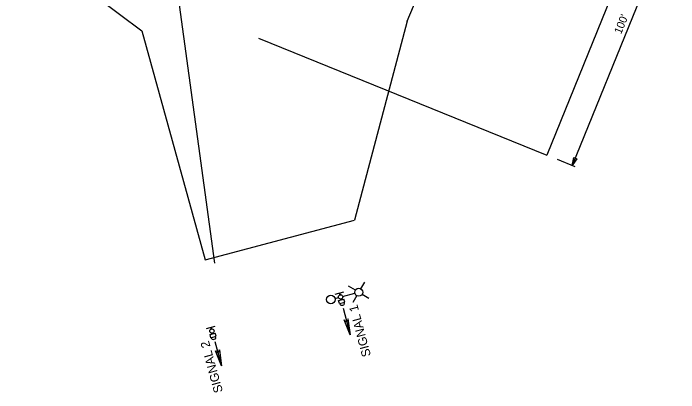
# Model space of a CAD drawing. Extents: x 2047712 to 2051245, y 280285 to 283042.
# Drawn here: x 2047805.4 to 2048040.6, y 281659.1 to 281793.2 of the extents above; entities that cross this region are included whole.
import ezdxf

# ---------------------------------------------------------------- set-up
doc = ezdxf.new("R2010")
doc.units = 0
for name, color, linetype in [('RD_X_GR_Rt', 7, 'Continuous'), ('RW_X_CL_100_Distances', 7, 'Continuous'), ('RW_X_CL_100_Stations', 7, 'Continuous'), ('SV_Control_Point', 7, 'Continuous')]:
    doc.layers.add(name, color=color, linetype=linetype)

msp = doc.modelspace()

# ---------------------------------------------------------------- linework, layer by layer
at = {"layer": 'RD_X_GR_Rt'}
for p, q in [((2048031.58, 281835.68), (2047993.97, 281743.02)), ((2048040.59, 281832.02), (2048002.98, 281739.36)), ((2047892.05, 281784.39), (2047993.97, 281743.02)), ((2047997.58, 281741.56), (2048003.91, 281738.99))]:
    msp.add_line(p, q, dxfattribs=at)
msp.add_lwpolyline([(2048003.51, 281742.17), (2048004.55, 281741.75), (2048002.98, 281739.36)], close=True, dxfattribs=at)
at = {"layer": 'RW_X_CL_100_Distances'}
msp.add_line((2047876.59, 281704.89), (2047860.7, 281821.73), dxfattribs=at)
at = {"layer": 'RW_X_CL_100_Stations'}
for p, q in [((2047928.22, 281695.78), (2047929.65, 281698.19)), ((2047926.31, 281695.28), (2047923.89, 281696.71)), ((2047919.14, 281693.85), (2047922.27, 281694.69)), ((2047920.59, 281694.24), (2047920.76, 281693.6)), ((2047920.82, 281694.3), (2047921, 281693.66)), ((2047921.81, 281693.1), (2047926.16, 281694.22)), ((2047926.8, 281693.37), (2047925.38, 281690.95)), ((2047928.72, 281693.86), (2047931.13, 281692.44)), ((2047919.12, 281692.4), (2047920.34, 281692.71)), ((2047920.4, 281691.68), (2047922.27, 281692.18)), ((2047920.69, 281690.57), (2047920.4, 281691.68)), ((2047920.69, 281690.57), (2047922.57, 281691.07)), ((2047921.15, 281692.16), (2047921.22, 281691.9)), ((2047921.38, 281692.22), (2047921.45, 281691.96)), ((2047922.57, 281691.07), (2047922.27, 281692.18)), ((2047922.45, 281690.54), (2047922.33, 281691)), ((2047921.06, 281690.16), (2047920.94, 281690.63)), ((2047921.99, 281688.91), (2047924.47, 281679.57)), ((2047924.47, 281679.57), (2047922.35, 281684.83)), ((2047923.7, 281685.19), (2047924.47, 281679.57)), ((2047873.66, 281681.76), (2047876.78, 281682.63)), ((2047875.11, 281682.16), (2047875.29, 281681.52)), ((2047875.34, 281682.22), (2047875.52, 281681.59)), ((2047874.94, 281679.6), (2047876.81, 281680.12)), ((2047875.25, 281678.5), (2047874.94, 281679.6)), ((2047875.69, 281680.08), (2047875.76, 281679.83)), ((2047875.92, 281680.15), (2047875.99, 281679.89)), ((2047877.12, 281679.02), (2047876.81, 281680.12)), ((2047875.25, 281678.5), (2047877.12, 281679.02)), ((2047875.62, 281678.09), (2047875.49, 281678.56)), ((2047876.67, 281677.22), (2047879.06, 281668.6)), ((2047877.01, 281678.48), (2047876.88, 281678.94)), ((2047879.06, 281668.6), (2047876.88, 281673.83)), ((2047878.24, 281674.21), (2047879.06, 281668.6))]:
    msp.add_line(p, q, dxfattribs=at)
for centre, radius in [((2047927.51, 281694.57), 1.4), ((2047917.67, 281692.02), 1.5), ((2047921.07, 281692.91), 0.757), ((2047875.6, 281680.84), 0.757)]:
    msp.add_circle(centre, radius, dxfattribs=at)
for centre, start, end in [((2047923.02, 281685.01), 194.8636, 14.8636), ((2047877.56, 281674.02), 195.4543, 15.4543)]:
    msp.add_arc(centre, 0.702, start, end, dxfattribs=at)
for centre, major_axis in [((2047921.76, 281690.35), (-0.696, -0.186)), ((2047876.31, 281678.28), (-0.694, -0.193))]:
    msp.add_ellipse(centre, major_axis=major_axis, ratio=0.45371, start_param=0, end_param=3.141593, dxfattribs=at)
at = {"layer": 'SV_Control_Point'}
for p, q in [((2047944.6, 281790.37), (2047966.98, 281842.6)), ((2047805.42, 281821.12), (2047850.83, 281786.96)), ((2047944.6, 281790.37), (2047925.99, 281720.08)), ((2047850.83, 281786.96), (2047873.25, 281706.08)), ((2047873.25, 281706.08), (2047925.99, 281720.08))]:
    msp.add_line(p, q, dxfattribs=at)

# ---------------------------------------------------------------- texts
at = {"layer": 'RD_X_GR_Rt'}
msp.add_text("100'", height=2.8, rotation=67.9067, dxfattribs=at).set_placement((2048020.24, 281785.61))
at = {"layer": 'RW_X_CL_100_Stations'}
for s, rotation, p in [('SIGNAL 1', 104.8636, (2047931.84, 281672.21)), ('SIGNAL 2', 105.4543, (2047879.53, 281659.49))]:
    msp.add_text(s, height=3.125, rotation=rotation, dxfattribs=at).set_placement(p)

doc.saveas('drawing.dxf')
